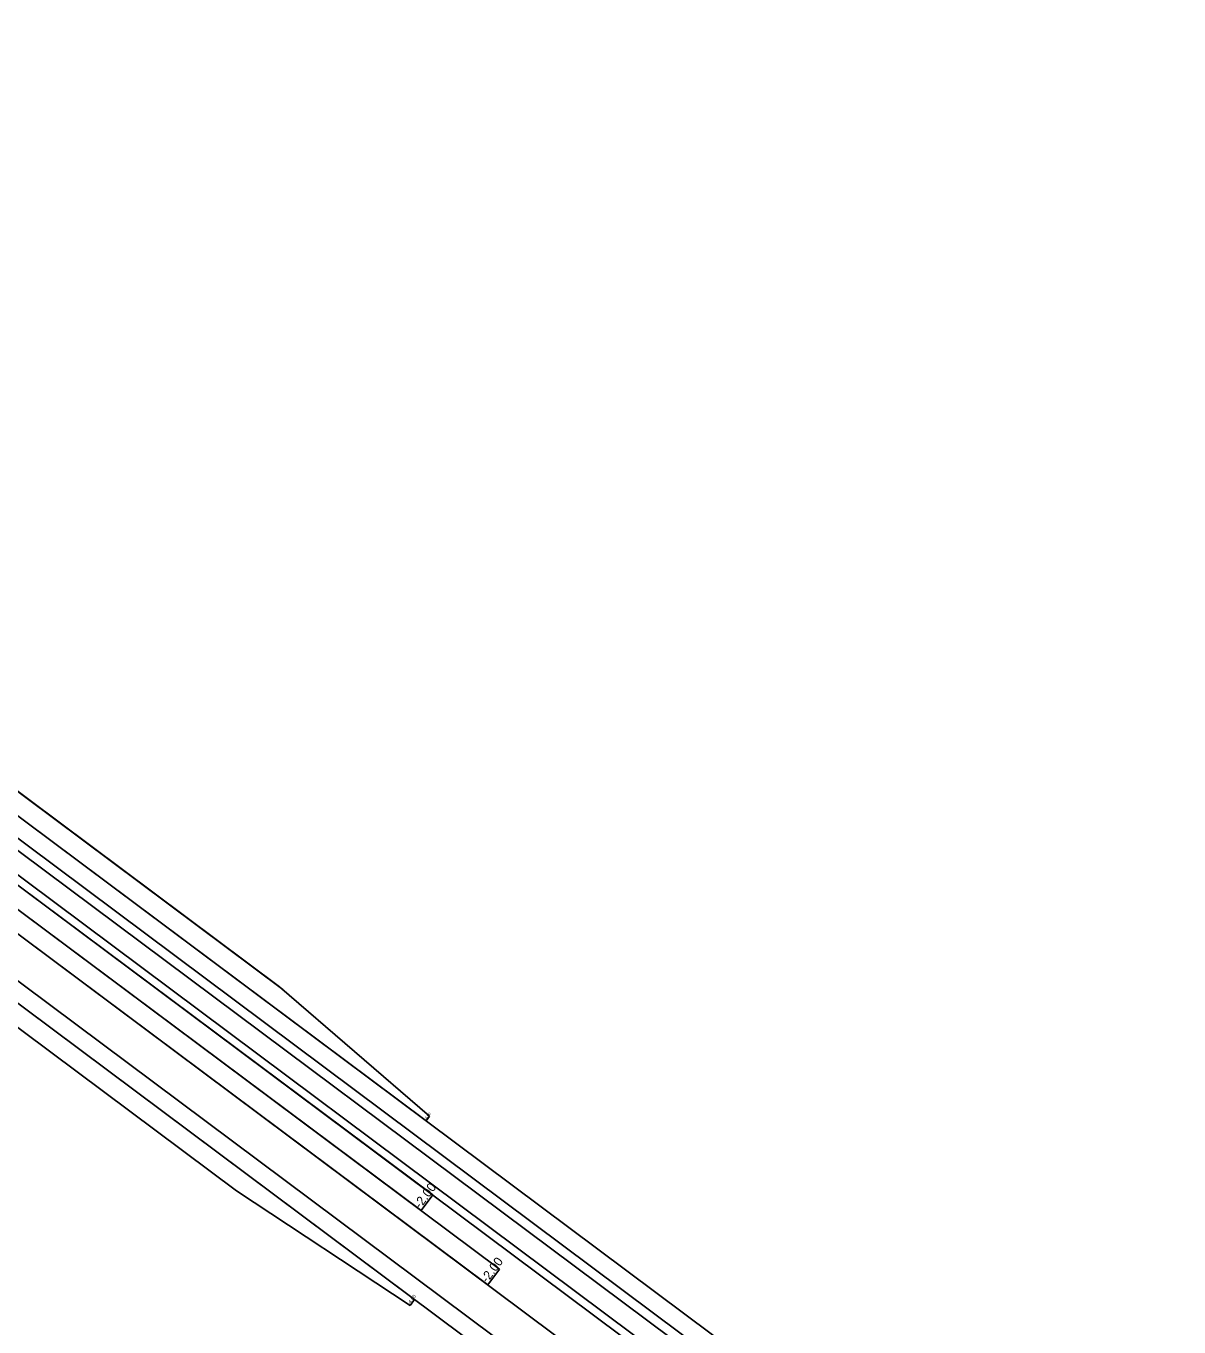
# Model space of a CAD drawing. Extents: x 2342222 to 2351711, y 366548 to 372860.
# Drawn here: x 2342929 to 2343637, y 372059 to 372857 of the extents above; entities that cross this region are included whole.
import ezdxf

# ---------------------------------------------------------------- set-up
doc = ezdxf.new("R2010")
doc.units = 0
for name, color, linetype in [('RD_PD_PaveShd', 7, 'Continuous'), ('RD_PD_SuperShp_BL_EB_526', 7, 'Continuous'), ('RD_PD_SuperShp_BL_WB_526', 7, 'Continuous'), ('RD_PD_SuperShp_WB_526', 7, 'Continuous')]:
    doc.layers.add(name, color=color, linetype=linetype)

msp = doc.modelspace()

# ---------------------------------------------------------------- linework, layer by layer
at = {"layer": 'RD_PD_PaveShd'}
for p, q in [((2342250.76, 372817.76), (2343171.62, 372130.46)), ((2343086.74, 372266.18), (2342394.78, 372782.64)), ((2343176.88, 372188.4), (2343084.76, 372267.66)), ((2343178.8, 372140.08), (2343171.62, 372130.46))]:
    msp.add_line(p, q, dxfattribs=at)
at = {"layer": 'RD_PD_SuperShp_BL_EB_526'}
for p, q in [((2343219.8, 372094.5), (2342250.75, 372817.76)), ((2342242.24, 372809.14), (2343465.01, 371896.51)), ((2342243.58, 372808.14), (2343212.62, 372084.88)), ((2343451.25, 371878.08), (2342228.48, 372790.71)), ((2343451.25, 371878.08), (2342228.48, 372790.71)), ((2342221.9, 372781.89), (2343444.67, 371869.26)), ((2343167.66, 372076.01), (2342239.02, 372769.12)), ((2342326.11, 372689.14), (2343058.44, 372142.56)), ((2343058.44, 372142.56), (2343164.88, 372072.28)), ((2343212.62, 372084.88), (2343219.8, 372094.5)), ((2343164.88, 372072.28), (2343167.66, 372076.01))]:
    msp.add_line(p, q, dxfattribs=at)
at = {"layer": 'RD_PD_SuperShp_BL_WB_526'}
for p, q in [((2343465.22, 371968.72), (2342276.93, 372855.62)), ((2343458.64, 371959.91), (2342270.35, 372846.81)), ((2342270.35, 372846.81), (2343458.64, 371959.91)), ((2342294.19, 372842.74), (2343174.73, 372185.53)), ((2342256.59, 372828.37), (2343444.88, 371941.48)), ((2343178.79, 372140.08), (2342257.93, 372827.37)), ((2342250.75, 372817.76), (2343171.61, 372130.46)), ((2343084.76, 372267.66), (2342394.78, 372782.64)), ((2343176.88, 372188.4), (2343084.76, 372267.66)), ((2343174.73, 372185.53), (2343176.88, 372188.4)), ((2343171.61, 372130.46), (2343178.79, 372140.08))]:
    msp.add_line(p, q, dxfattribs=at)
at = {"layer": 'RD_PD_SuperShp_WB_526'}
for p, q in [((2345214.29, 370642.07), (2342246.73, 372856.95)), ((2342239.55, 372847.33), (2345207.11, 370632.45))]:
    msp.add_line(p, q, dxfattribs=at)

# ---------------------------------------------------------------- texts
at = {"layer": 'RD_PD_SuperShp_BL_EB_526'}
for s, height, p in [('-2.00', 5.52, (2343212.24, 372085.77)), ('-4.00', 2.141, (2343164.68, 372072.56))]:
    msp.add_text(s, height=height, rotation=53.26372, dxfattribs=at).set_placement(p)
at = {"layer": 'RD_PD_SuperShp_BL_WB_526'}
for s, height, rotation, p in [('-4.00', 1.649, 53.21609, (2343174.62, 372185.8)), ('-2.00', 5.52, 53.26372, (2343171.23, 372131.35))]:
    msp.add_text(s, height=height, rotation=rotation, dxfattribs=at).set_placement(p)

doc.saveas('drawing.dxf')
